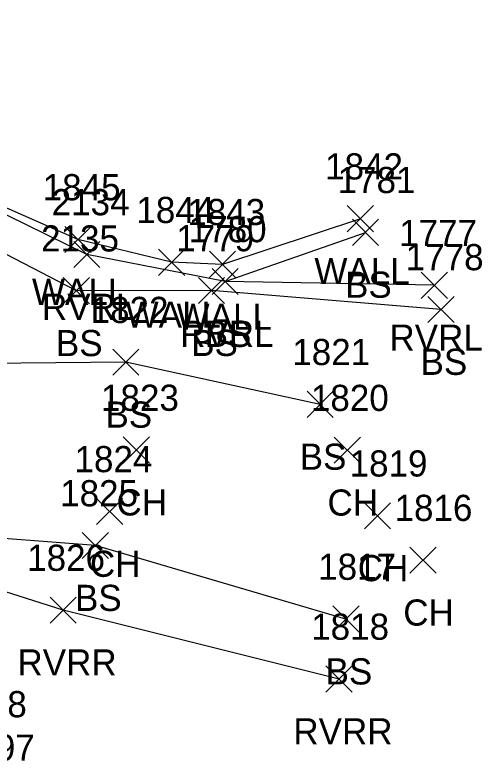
# Model space of a CAD drawing. Extents: x 1653135 to 1655489, y 602711 to 605684.
# Drawn here: x 1653851.9 to 1653887.6, y 605199.6 to 605256.6 of the extents above; entities that cross this region are included whole.
import ezdxf

# ---------------------------------------------------------------- set-up
doc = ezdxf.new("R2010")
doc.units = 0
for name, color, linetype in [('L_A', 7, 'Continuous'), ('L_I', 7, 'Continuous'), ('L_TIC', 7, 'Continuous'), ('LAWE', 7, 'Continuous'), ('LELB', 7, 'Continuous'), ('LW', 7, 'Continuous'), ('R_I', 7, 'Continuous')]:
    doc.layers.add(name, color=color, linetype=linetype)

msp = doc.modelspace()

# ---------------------------------------------------------------- linework, layer by layer
at = {"layer": 'L_TIC'}
for points in [[(1653877.271, 605240.042), (1653879.271, 605242.042)], [(1653879.271, 605240.042), (1653877.271, 605242.042)], [(1653877.271, 605240.042), (1653879.271, 605242.042)], [(1653879.271, 605240.042), (1653877.271, 605242.042)], [(1653877.66, 605239.001), (1653879.66, 605241.001)], [(1653879.66, 605239.001), (1653877.66, 605241.001)], [(1653877.66, 605239.001), (1653879.66, 605241.001)], [(1653879.66, 605239.001), (1653877.66, 605241.001)], [(1653855.7, 605238.451), (1653857.7, 605240.451)], [(1653857.7, 605238.451), (1653855.7, 605240.451)], [(1653855.7, 605238.451), (1653857.7, 605240.451)], [(1653857.7, 605238.451), (1653855.7, 605240.451)], [(1653856.382, 605237.306), (1653858.382, 605239.306)], [(1653858.382, 605237.306), (1653856.382, 605239.306)], [(1653856.382, 605237.306), (1653858.382, 605239.306)], [(1653858.382, 605237.306), (1653856.382, 605239.306)], [(1653862.854, 605236.712), (1653864.854, 605238.712)], [(1653864.854, 605236.712), (1653862.854, 605238.712)], [(1653862.854, 605236.712), (1653864.854, 605238.712)], [(1653864.854, 605236.712), (1653862.854, 605238.712)], [(1653866.743, 605236.554), (1653868.743, 605238.554)], [(1653868.743, 605236.554), (1653866.743, 605238.554)], [(1653866.743, 605236.554), (1653868.743, 605238.554)], [(1653868.743, 605236.554), (1653866.743, 605238.554)], [(1653866.94, 605235.243), (1653868.94, 605237.243)], [(1653868.94, 605235.243), (1653866.94, 605237.243)], [(1653866.94, 605235.243), (1653868.94, 605237.243)], [(1653868.94, 605235.243), (1653866.94, 605237.243)], [(1653866.94, 605235.243), (1653868.94, 605237.243)], [(1653868.94, 605235.243), (1653866.94, 605237.243)], [(1653866.94, 605235.243), (1653868.94, 605237.243)], [(1653868.94, 605235.243), (1653866.94, 605237.243)], [(1653882.926, 605234.955), (1653884.926, 605236.955)], [(1653884.926, 605234.955), (1653882.926, 605236.955)], [(1653882.926, 605234.955), (1653884.926, 605236.955)], [(1653884.926, 605234.955), (1653882.926, 605236.955)], [(1653855.576, 605234.537), (1653857.576, 605236.537)], [(1653857.576, 605234.537), (1653855.576, 605236.537)], [(1653855.576, 605234.537), (1653857.576, 605236.537)], [(1653857.576, 605234.537), (1653855.576, 605236.537)], [(1653865.904, 605234.551), (1653867.904, 605236.551)], [(1653867.904, 605234.551), (1653865.904, 605236.551)], [(1653865.904, 605234.551), (1653867.904, 605236.551)], [(1653867.904, 605234.551), (1653865.904, 605236.551)], [(1653883.427, 605233.105), (1653885.427, 605235.105)], [(1653885.427, 605233.105), (1653883.427, 605235.105)], [(1653883.427, 605233.105), (1653885.427, 605235.105)], [(1653885.427, 605233.105), (1653883.427, 605235.105)], [(1653859.359, 605229.071), (1653861.359, 605231.071)], [(1653861.359, 605229.071), (1653859.359, 605231.071)], [(1653859.359, 605229.071), (1653861.359, 605231.071)], [(1653861.359, 605229.071), (1653859.359, 605231.071)], [(1653874.197, 605225.853), (1653876.197, 605227.853)], [(1653876.197, 605225.853), (1653874.197, 605227.853)], [(1653874.197, 605225.853), (1653876.197, 605227.853)], [(1653876.197, 605225.853), (1653874.197, 605227.853)], [(1653860.154, 605222.357), (1653862.154, 605224.357)], [(1653862.154, 605222.357), (1653860.154, 605224.357)], [(1653860.154, 605222.357), (1653862.154, 605224.357)], [(1653862.154, 605222.357), (1653860.154, 605224.357)], [(1653876.271, 605222.346), (1653878.271, 605224.346)], [(1653878.271, 605222.346), (1653876.271, 605224.346)], [(1653876.271, 605222.346), (1653878.271, 605224.346)], [(1653878.271, 605222.346), (1653876.271, 605224.346)], [(1653858.128, 605217.668), (1653860.128, 605219.668)], [(1653860.128, 605217.668), (1653858.128, 605219.668)], [(1653858.128, 605217.668), (1653860.128, 605219.668)], [(1653860.128, 605217.668), (1653858.128, 605219.668)], [(1653878.582, 605217.335), (1653880.582, 605219.335)], [(1653880.582, 605217.335), (1653878.582, 605219.335)], [(1653878.582, 605217.335), (1653880.582, 605219.335)], [(1653880.582, 605217.335), (1653878.582, 605219.335)], [(1653857.032, 605215.058), (1653859.032, 605217.058)], [(1653859.032, 605215.058), (1653857.032, 605217.058)], [(1653857.032, 605215.058), (1653859.032, 605217.058)], [(1653859.032, 605215.058), (1653857.032, 605217.058)], [(1653882.061, 605213.939), (1653884.061, 605215.939)], [(1653884.061, 605213.939), (1653882.061, 605215.939)], [(1653882.061, 605213.939), (1653884.061, 605215.939)], [(1653884.061, 605213.939), (1653882.061, 605215.939)], [(1653854.567, 605210.126), (1653856.567, 605212.126)], [(1653856.567, 605210.126), (1653854.567, 605212.126)], [(1653854.567, 605210.126), (1653856.567, 605212.126)], [(1653856.567, 605210.126), (1653854.567, 605212.126)], [(1653876.173, 605209.439), (1653878.173, 605211.439)], [(1653878.173, 605209.439), (1653876.173, 605211.439)], [(1653876.173, 605209.439), (1653878.173, 605211.439)], [(1653878.173, 605209.439), (1653876.173, 605211.439)], [(1653875.64, 605204.858), (1653877.64, 605206.858)], [(1653877.64, 605204.858), (1653875.64, 605206.858)], [(1653875.64, 605204.858), (1653877.64, 605206.858)], [(1653877.64, 605204.858), (1653875.64, 605206.858)]]:
    msp.add_lwpolyline(points, dxfattribs=at)
at = {"layer": 'LAWE'}
for points in [[(1653883.926, 605235.955), (1653867.94, 605236.243), (1653857.382, 605238.306), (1653840.665, 605246.504), (1653832.978, 605251.978), (1653830.813, 605253.255), (1653828.359, 605253.973)], [(1653876.64, 605205.858), (1653855.567, 605211.126), (1653847.214, 605213.774), (1653830.294, 605221.821), (1653823.776, 605224.855), (1653818.947, 605224.471), (1653814.233, 605217.925)]]:
    msp.add_lwpolyline(points, dxfattribs=at)
at = {"layer": 'LELB'}
for points in [[(1653884.427, 605234.105), (1653866.904, 605235.551), (1653856.576, 605235.537), (1653838.985, 605244.661), (1653831.584, 605246.445), (1653830.813, 605253.255)], [(1653875.197, 605226.853), (1653860.359, 605230.071), (1653846.962, 605229.94), (1653824.69, 605239.68), (1653817.388, 605238.75)], [(1653867.94, 605236.243), (1653878.66, 605240.001)], [(1653877.173, 605210.439), (1653858.032, 605216.058), (1653847.347, 605216.866), (1653832.164, 605225.688), (1653817.479, 605230.045)]]:
    msp.add_lwpolyline(points, dxfattribs=at)
at = {"layer": 'LW'}
msp.add_lwpolyline([(1653878.271, 605241.042), (1653867.743, 605237.554), (1653863.854, 605237.712), (1653856.7, 605239.451), (1653842.894, 605245.551), (1653840.592, 605248.321), (1653835.494, 605252.137), (1653825.7, 605256.225), (1653824.797, 605256.62)], dxfattribs=at)

# ---------------------------------------------------------------- texts
at = {"layer": 'L_A'}
for s, p in [('WALL', (1653874.759, 605236.042)), ('WALL', (1653874.759, 605236.042)), ('BS', (1653877.101, 605235.001)), ('BS', (1653877.101, 605235.001)), ('WALL', (1653853.188, 605234.451)), ('WALL', (1653853.188, 605234.451)), ('RVRL', (1653853.949, 605233.306)), ('RVRL', (1653853.949, 605233.306)), ('WALL', (1653860.342, 605232.712)), ('WALL', (1653860.342, 605232.712)), ('WALL', (1653864.232, 605232.554)), ('WALL', (1653864.232, 605232.554)), ('RVRL', (1653864.507, 605231.243)), ('RVRL', (1653864.507, 605231.243)), ('BS', (1653866.381, 605231.243)), ('BS', (1653866.381, 605231.243)), ('RVRL', (1653880.493, 605230.955)), ('RVRL', (1653880.493, 605230.955)), ('BS', (1653855.017, 605230.537)), ('BS', (1653855.017, 605230.537)), ('BS', (1653865.345, 605230.551)), ('BS', (1653865.345, 605230.551)), ('BS', (1653882.868, 605229.105)), ('BS', (1653882.868, 605229.105)), ('BS', (1653858.8, 605225.071)), ('BS', (1653858.8, 605225.071)), ('BS', (1653873.638, 605221.853)), ('BS', (1653873.638, 605221.853)), ('CH', (1653859.642, 605218.357)), ('CH', (1653859.642, 605218.357)), ('CH', (1653875.759, 605218.346)), ('CH', (1653875.759, 605218.346)), ('CH', (1653857.616, 605213.668)), ('CH', (1653857.616, 605213.668)), ('CH', (1653878.07, 605213.335)), ('CH', (1653878.07, 605213.335)), ('BS', (1653856.473, 605211.058)), ('BS', (1653856.473, 605211.058)), ('CH', (1653881.549, 605209.939)), ('CH', (1653881.549, 605209.939)), ('RVRR', (1653852.079, 605206.126)), ('RVRR', (1653852.079, 605206.126)), ('BS', (1653875.614, 605205.439)), ('BS', (1653875.614, 605205.439)), ('RVRR', (1653873.152, 605200.858)), ('RVRR', (1653873.152, 605200.858))]:
    msp.add_text(s, height=2, dxfattribs=at).set_placement(p)
at = {"layer": 'L_I'}
for s, p in [('1842', (1653875.578, 605244.042)), ('1842', (1653875.578, 605244.042)), ('1781', (1653876.534, 605243.001)), ('1781', (1653876.534, 605243.001)), ('1845', (1653854.007, 605242.451)), ('1845', (1653854.007, 605242.451)), ('2134', (1653854.69, 605241.306)), ('2134', (1653854.69, 605241.306)), ('1844', (1653861.161, 605240.712)), ('1844', (1653861.161, 605240.712)), ('1843', (1653865.051, 605240.554)), ('1843', (1653865.051, 605240.554)), ('1780', (1653865.161, 605239.243)), ('1780', (1653865.161, 605239.243)), ('1780', (1653865.161, 605239.243)), ('1780', (1653865.161, 605239.243)), ('1777', (1653881.233, 605238.955)), ('1777', (1653881.233, 605238.955)), ('2135', (1653853.883, 605238.537)), ('2135', (1653853.883, 605238.537)), ('1779', (1653864.203, 605238.551)), ('1779', (1653864.203, 605238.551)), ('1778', (1653881.734, 605237.105)), ('1778', (1653881.734, 605237.105)), ('1822', (1653857.666, 605233.071)), ('1822', (1653857.666, 605233.071)), ('1821', (1653873.071, 605229.853)), ('1821', (1653873.071, 605229.853)), ('1823', (1653858.461, 605226.357)), ('1823', (1653858.461, 605226.357)), ('1820', (1653874.491, 605226.346)), ('1820', (1653874.491, 605226.346)), ('1824', (1653856.435, 605221.668)), ('1824', (1653856.435, 605221.668)), ('1819', (1653877.449, 605221.335)), ('1819', (1653877.449, 605221.335)), ('1825', (1653855.339, 605219.058)), ('1825', (1653855.339, 605219.058)), ('1816', (1653880.88, 605217.939)), ('1816', (1653880.88, 605217.939)), ('1826', (1653852.819, 605214.126)), ('1826', (1653852.819, 605214.126)), ('1817', (1653875.048, 605213.439)), ('1817', (1653875.048, 605213.439)), ('1818', (1653874.514, 605208.858)), ('1818', (1653874.514, 605208.858)), ('2098', (1653846.842, 605202.933)), ('2098', (1653846.842, 605202.933))]:
    msp.add_text(s, height=2, dxfattribs=at).set_placement(p)
at = {"layer": 'R_I'}
msp.add_text('2097', height=2, dxfattribs=at).set_placement((1653847.451, 605199.613))
msp.add_text('2097', height=2, dxfattribs=at).set_placement((1653847.451, 605199.613))

doc.saveas('drawing.dxf')
